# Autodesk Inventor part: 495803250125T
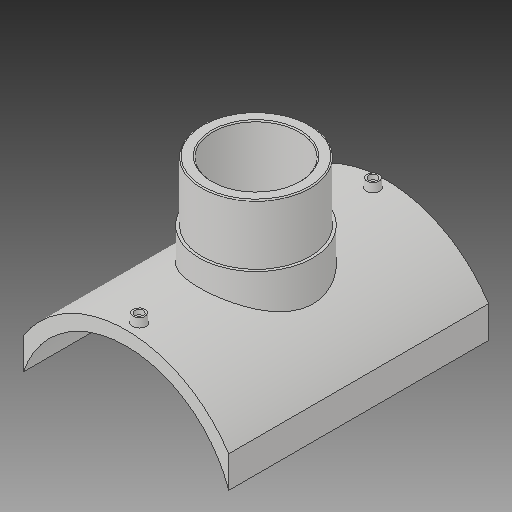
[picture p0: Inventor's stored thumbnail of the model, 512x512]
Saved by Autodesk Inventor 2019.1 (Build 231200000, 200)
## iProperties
Created: 2017-10
Part Number: 495803250125T
Material: Generic
Description: PLASSON BRANCH SADDLE 250x125
Document SubType Name: Modeling
Designer: KIM
Mass: 2754.05 g
Surface Area: 3037.44 cm^2
Volume: 2754.05 cm^3
Density: 1 g/cm^3
Appearance: Default
Author: KIM
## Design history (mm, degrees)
derived "495803.ipt"
feature "Solid1::495803.ipt"
tag "TaggingFeature1"
body "Solid1"
other parameters: "d1" = 16, "d2" = 237, "d4" = 0, "d12" = 150.6, "d13" = 14, "d14" = 135, "d16" = 5 deg, "d18" = 4, "d19" = 14, "d20" = 0, "d21" = 3, "d22" = 0, "d24" = 131.25, "d25" = 16, "d28" = 0, "d29" = 9.6, "d31" = 0, "d32" = 49.5, "d33" = 0, "d34" = 2.5, "d36" = 125, "d37" = 69.3, "d38" = 0, "d39" = 1.25, "d_1" = 125, "B_" = 237, "H_" = 99, "x_" = 16, "D_" = 16
